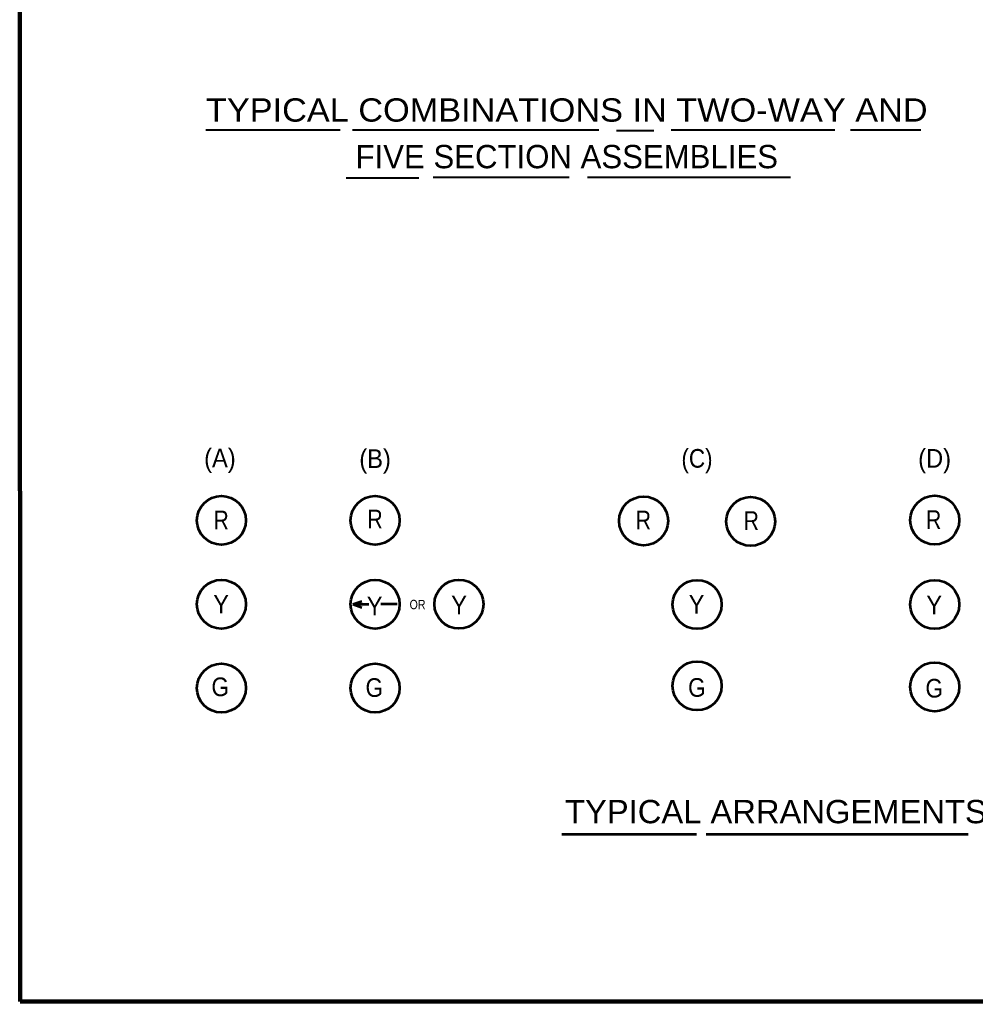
# Model space of a CAD drawing. Extents: x -382 to 473, y -132 to 412.
# Drawn here: x -325 to -78.9, y -120.3 to 132.5 of the extents above; entities that cross this region are included whole.
import ezdxf
from ezdxf.enums import TextEntityAlignment as Align

# ---------------------------------------------------------------- set-up
doc = ezdxf.new("R2010")
doc.units = 0
doc.header["$LTSCALE"] = 1.1
doc.layers.add('1', color=7, linetype='Continuous', lineweight=53)

msp = doc.modelspace()

# ---------------------------------------------------------------- linework, layer by layer
at = {"layer": '1', "lineweight": 40}
for p, q in [((-277.059, 104.115), (-242.473, 104.115)), ((-239.329, 104.115), (-175.832, 104.115)), ((-171.337, 103.918), (-161.69, 103.918)), ((-157.189, 104.115), (-115.114, 104.115)), ((-111.009, 104.115), (-92.93, 104.115)), ((-240.901, 91.731), (-222.216, 91.731)), ((-218.499, 91.927), (-183.501, 91.927)), ((-178.805, 91.927), (-126.515, 91.927))]:
    msp.add_line(p, q, dxfattribs=at)
at = {"layer": '1'}
for p, q in [((-239.179, -18.055), (-236.924, -17.234)), ((-239.179, -18.055), (-235.083, -18.055)), ((-239.179, -18.055), (-236.924, -18.876)), ((-227.779, -18.055), (-231.979, -18.055)), ((-185.34, -77.252), (-150.683, -77.252)), ((-148.192, -77.252), (-80.761, -77.252))]:
    msp.add_line(p, q, dxfattribs=at)
at = {"layer": '1', "lineweight": 158}
msp.add_line((466.693, -120.327), (-324.907, -120.327), dxfattribs=at)
msp.add_lwpolyline([(466.693, 405.773), (-325.007, 405.673), (-324.907, -120.327)], dxfattribs=at)
at = {"layer": '1'}
for centre in [(-273.053, 3.538), (-233.479, 3.538), (-164.321, 3.404), (-136.753, 3.255), (-89.358, 3.61), (-273.053, -18.055), (-233.479, -18.055), (-211.871, -18.049), (-150.542, -18.134), (-89.358, -18.134), (-150.542, -39.072), (-273.053, -39.647), (-233.479, -39.647), (-89.358, -39.341)]:
    msp.add_circle(centre, 6.3, dxfattribs=at)

# ---------------------------------------------------------------- texts
for s, height, width, p in [('TYPICAL COMBINATIONS IN TWO-WAY AND', 6, 1.1, (-184.11, 106.211)), ('(A)', 4.8, 0.95, (-273.428, 17.21)), ('(B)', 4.8, 0.95, (-233.472, 17.032)), ('(C)', 4.8, 0.9, (-150.573, 17.102)), ('(D)', 4.8, 0.95, (-89.385, 17.102)), ('R', 4.8, 0.85, (-164.385, 1.227)), ('R', 4.8, 0.85, (-136.593, 1.079)), ('R', 4.8, 0.85, (-89.638, 1.332)), ('OR', 2.4, 0.85, (-222.54, -19.334)), ('Y', 4.8, 0.95, (-150.687, -20.458)), ('Y', 4.8, 0.95, (-89.489, -20.64)), ('G', 4.8, 0.9, (-150.611, -41.893)), ('G', 4.8, 0.9, (-89.489, -42.091)), ('TYPICAL ARRANGEMENTS OF LENSES IN FACES', 6, 1.05, (-84.845, -74.459))]:
    msp.add_text(s, height=height, dxfattribs=dict(at, width=width)).set_placement(p, align=Align.CENTER)
msp.add_text('FIVE SECTION ASSEMBLIES', height=6, dxfattribs=at).set_placement((-184.11, 94.211), align=Align.CENTER)
for s, width, p in [('R', 0.85, (-275.083, 1.241)), ('R', 0.85, (-235.446, 1.488)), ('Y', 0.95, (-275.157, -20.447)), ('Y', 0.95, (-235.627, -20.9)), ('Y', 0.95, (-213.877, -20.673)), ('G', 0.9, (-275.608, -41.731)), ('G', 0.9, (-235.931, -41.919))]:
    msp.add_text(s, height=4.8, dxfattribs=dict(at, width=width)).set_placement(p)

doc.saveas('drawing.dxf')
